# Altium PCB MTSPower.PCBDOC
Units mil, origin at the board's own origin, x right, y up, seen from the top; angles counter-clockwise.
Board outline 6000 x 4000 mil, 2 copper layers (Top Layer, Bottom Layer); 21 components, 5 nets, 48 pads, 4 vias.
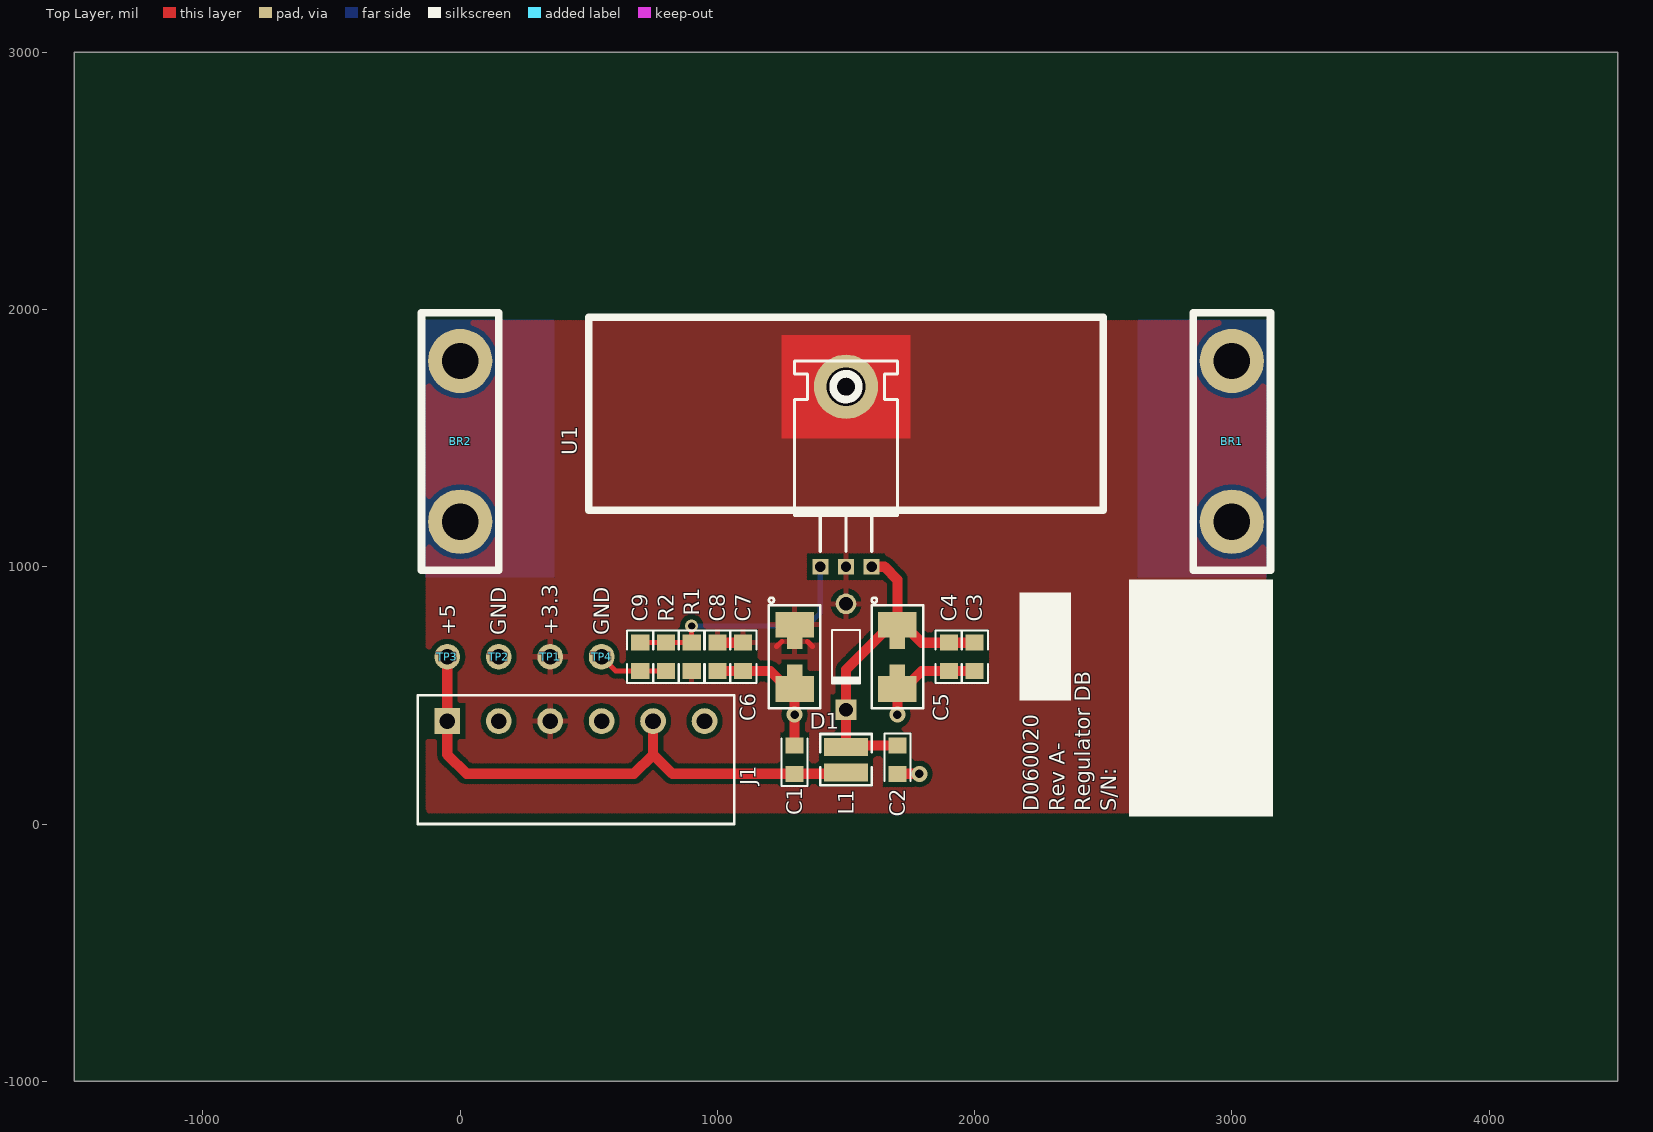
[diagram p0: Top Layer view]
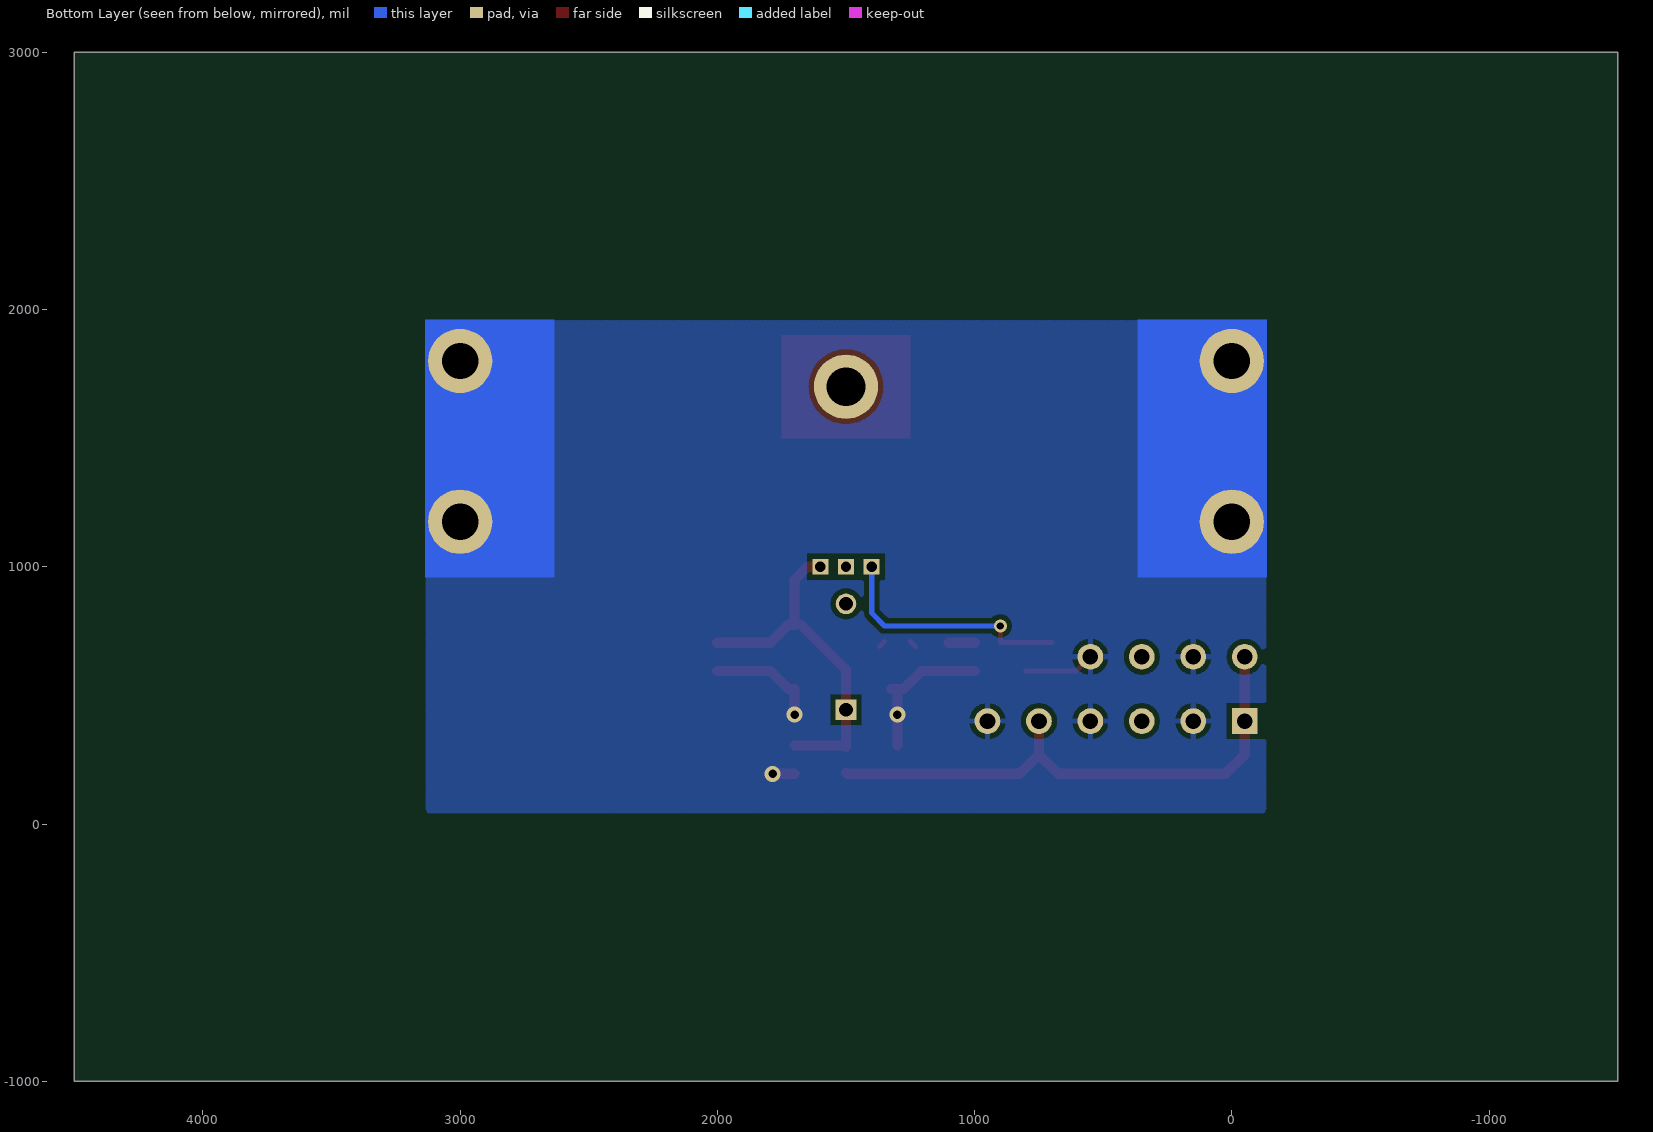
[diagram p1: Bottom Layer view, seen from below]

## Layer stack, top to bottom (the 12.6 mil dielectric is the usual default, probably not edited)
Top Layer: signal copper 1.4
Dielectric: dielectric 12.6, FR-4, Dk 4.8
Bottom Layer: signal copper 1.4

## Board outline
-1500,-1000 4500,-1000 4500,3000 -1500,3000

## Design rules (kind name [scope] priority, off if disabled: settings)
Clearance Clearance_1 [InPoly] p1: gap=20
Clearance [All] p2: gap=10
ComponentClearance [All] p1 off: gap=10 collisioncheckmode=0
HoleSize [All] p1: absolutevalues=TRUE maxlimit=250 minlimit=1 maxpercent=80.000 minpercent=20.000
PolygonConnect [All] p1: connectstyle=Relief reliefconductorwidth=20 reliefentries=4 polygonreliefangle="90 Angle"
RoomDefinition MTSPower [InComponentClass('MTSPower')] p1: confinementstyle=ConfineOut formatcopy=TRUE lockcomponents=FALSE outline 500,2100 500,2200 700,2200 700,2100
RoutingVias [All] p1: holewidth=28 width=50 viastyle="Through Hole" minholewidth=28 minwidth=50 maxholewidth=100 maxwidth=100
SolderMaskExpansion [All] p1: expansion=4
TestPointUsage [All] p1: valid=0 allowmultiple=FALSE
Testpoint [All] p1: side=15 testpointundercomponent=TRUE minsize=40 maxsize=100 preferedsize=60 minholesize=0 maxholesize=40 preferedholesize=32 testpointgrid=1 style=1023 order=0-112345678
Width [All] p1: maxlimit=100 minlimit=10 preferedwidth=10 toplayer_prefwidth=20 minimp=50.000000 maximp=50.000000 favimp=50.000000
16 further rules are at their usual default settings.

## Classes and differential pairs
component class MTSPower: BR1 BR2 C3 C4 C5 C6 C7 C8 C9 D1 J1 L1 R1 R2 TP1 TP2 TP3 TP4 U1

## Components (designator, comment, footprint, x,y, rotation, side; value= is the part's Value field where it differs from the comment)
BR1 "Header 2" "RA Bracket" 3000,1800 r180 top
BR2 "Header 2" "RA Bracket" 0,1800 r180 top
C1 "10uF" CC3216-1206 1300,250 r180 top
C2 "10uF" CC3216-1206 1700,250 r0 top
C3 "4.7uF" CR3216-1206 2000,650 r90 top
C4 "4.7uF" CR3216-1206 1900,650 r90 top
C5 "Tant." 2512_1206 1700,650 r270 top
C6 "Tant." 2512_1206 1300,650 r270 top
C7 "4.7uF" CR3216-1206 1100,650 r90 top
C8 "4.7uF" CR3216-1206 1000,650 r90 top
C9 "4.7uF" CR3216-1206 700,650 r90 top
D1 "Diode 1N4001" DIO10.46-5.3x2.8 1500,650 r270 top
J1 "Header 6" "TB Header, 6 Pos" 450,400 r0 top
L1 "10uH" CR3232-1212 1500,250 r180 top
R1 "NL" CR3216-1206 900,650 r270 top
R2 "0" CR3216-1206 800,650 r90 top
TP1 "+3.3" TP1 350,650 r0 top
TP2 "GND" TP1 150,650 r0 top
TP3 "+5" TP1 -50,650 r0 top
TP4 "GND" TP1 550,650 r0 top
U1 "LM1085-3.3" TO-220+BHS 1500,1700 r0 top

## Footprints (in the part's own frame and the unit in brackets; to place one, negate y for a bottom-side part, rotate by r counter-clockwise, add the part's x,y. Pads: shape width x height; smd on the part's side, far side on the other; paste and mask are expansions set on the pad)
2512_1206 [mil] "2512 Package with pads for 1206"
  rect 100x150 smd: 1(-125,0) 2(125,0)
  rect 60x60 smd: 1(-60,0) 2(60,0)
  silkscreen extent -230,-100 200,100
CC3216-1206 [mm]
  rect 1.8x1.6 smd: 1(0,1.4) 2(0,-1.4)
  silkscreen extent -1.3,-2.1 1.3,2.6
CR3216-1206 [mm]
  rect 1.6x1.8 smd: 1(-1.4,0) 2(1.4,0)
  silkscreen extent -2.6,-1.3 2.6,1.3
CR3232-1212 [mil]
  rect 170x70 smd: 1(0,50) 2(0,-50)
  silkscreen extent -100,-100 100,100
DIO10.46-5.3x2.8 [mil] "Diode, Axial; Body 5.2 x 2.7 mm (LxDia. max), Lead Dia. 0.86 mm (max)"
  round 80 hole 53.5: 1(-205.91,0)
  rect 80x80 hole 53.5: 2(205.91,0)
  silkscreen extent -104,-55 108,55
"RA Bracket" [mil]
  round 250 hole 141: 1(0,0) 2(0,625)
  silkscreen extent -150,-187 150,813
"TB Header, 6 Pos" [mil]
  rect 100x100 hole 61: 1(-500,0)
  round 100 hole 61: 2(-300,0) 3(-100,0) 4(100,0) 5(300,0) 6(500,0)
  silkscreen extent -615,-400 615,100
TO-220+BHS [mil]
  round 250 hole 151: 0(0,0)
  rect 62x62 hole 40: 1(-100,-700) 2(0,-700) 3(100,-700)
  silkscreen extent -1000,-640 1000,270
TP1 [mil]
  round 100 hole 61: 1(0,0)

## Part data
BR1 BR2: "Header, 2-Pin"
C1 C2 C5 C6: library part "Cap Pol1", "Polarized Capacitor (Radial)"
C3 C4 C7 C8 C9: library part "Cap Semi", "Capacitor (Semiconductor SIM Model)"
D1: "1 Amp General Purpose Rectifier"
J1: "Header, 6-Pin"
L1: library part "Inductor Iron", "Magnetic-Core Inductor"
R1 R2: library part res1, "Resistor"
TP1 TP2 TP3 TP4: library part TP
U1: library part LM317AT, "3-Terminal Adjustable Regulator"

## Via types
v1: diameter 62, hole 33, Top Layer to Bottom Layer, 3 vias
v2: diameter 50, hole 28, Top Layer to Bottom Layer, 1 vias

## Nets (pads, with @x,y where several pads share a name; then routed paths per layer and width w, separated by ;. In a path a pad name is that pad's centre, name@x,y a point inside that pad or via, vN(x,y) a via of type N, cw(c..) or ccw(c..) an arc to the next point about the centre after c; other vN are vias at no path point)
+3.3: C6.1 C7.2 C8.2 D1.1 J1.3 R1.2 TP1.1 U1.0 U1.2 | length 156.6
  Top Layer w20: 1230,690 1250,710 ; 1350,710 1370,690
  Top Layer w40: C8.2 C7.2
+5: C1.1 J1.1 J1.5 L1.1 TP3.1 | length 2155.5
  Top Layer w40: TP3.1 J1.1 -50,270 25.12,194.88 674.88,194.88 750,270 ; J1.5 750,270 ; L1.1 1494.88,194.88 825.12,194.88 750,270
GND: BR1.1 BR1.2 BR2.1 BR2.2 C1.2 C2.2 C3.1 C4.1 C5.2 C6.2 C7.1 C8.1 C9.1 J1.2 J1.4 J1.6 R2.1 TP2.1 TP4.1 | length 1360.6
  Top Layer w20: TP4.1 605.12,594.88 R2.1
  Top Layer w40: C8.1 1205.12,594.88 1275,525 C6.2@1300,525 ; C1.2 C6.2@1300,525 ; C6.2@1325,525 C6.2@1300,525 ; C2.2 v1(1785,195) ; v1(1700,425) 1700,525 1725,525 1794.88,594.88 C3.1
  other v1: 1300,425
NetC2_1: C2.1 C3.2 C4.2 C5.1 D1.2 L1.2 U1.3 | length 1374.3
  Top Layer w40: U1.3 1650,1000 1700,950 1700,775 1725,775 1794.88,705.12 C3.2 ; C5.1@1675,775 1500,600 L1.2 1505.12,305.12 C2.1
NetC9_2: C9.2 R1.1 R2.2 U1.1 | length 965.6
  Top Layer w20: C9.2 R1.1 v2(900,770)
  Bottom Layer w20: v2(900,770) 1350,770 1400,820 U1.1

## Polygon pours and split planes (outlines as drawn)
+3.3 on Top Layer (hatched 90Degree grid 10 track 20, remove dead copper): -125,1950 -125,50 3125,50 3125,1950
GND on Bottom Layer (hatched 90Degree grid 10 track 20, remove dead copper): -125,1950 -125,50 3125,50 3125,1950

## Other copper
Top Layer:
  region net +3.3: 1250,1900 1250,1500 1500,1500 1750,1500 1750,1900 1500,1900
Bottom Layer:
  region net GND: 3135,1960 3135,960 2635,960 2635,1960
  region net GND: -135,1960 -135,960 365,960 365,1960

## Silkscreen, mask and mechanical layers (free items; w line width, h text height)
Top Overlay:
  region: 3160,30 3160,950 2600,950 2600,30
  region: 2375,480 2375,900 2175,900 2175,480
  text "D060020" at 2250,50 h60 r90
  text "Rev A-" at 2350,50 h60 r90
  text "Regulator DB" at 2450,50 h60 r90
  text "S/N:" at 2550,50 h60 r90
Mechanical 1:
  lines w20: -180,0 3180,0 3180,2000 -180,2000 -180,0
